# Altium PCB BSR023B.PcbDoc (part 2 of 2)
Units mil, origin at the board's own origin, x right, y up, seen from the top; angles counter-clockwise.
Board outline 3000 x 3000 mil, 4 copper layers (Top Layer, MidLayer 1, Mid Layer 2, Bottom Layer), stack 60.8 mil thick; 95 components, 24 nets, 183 pads, 215 vias.
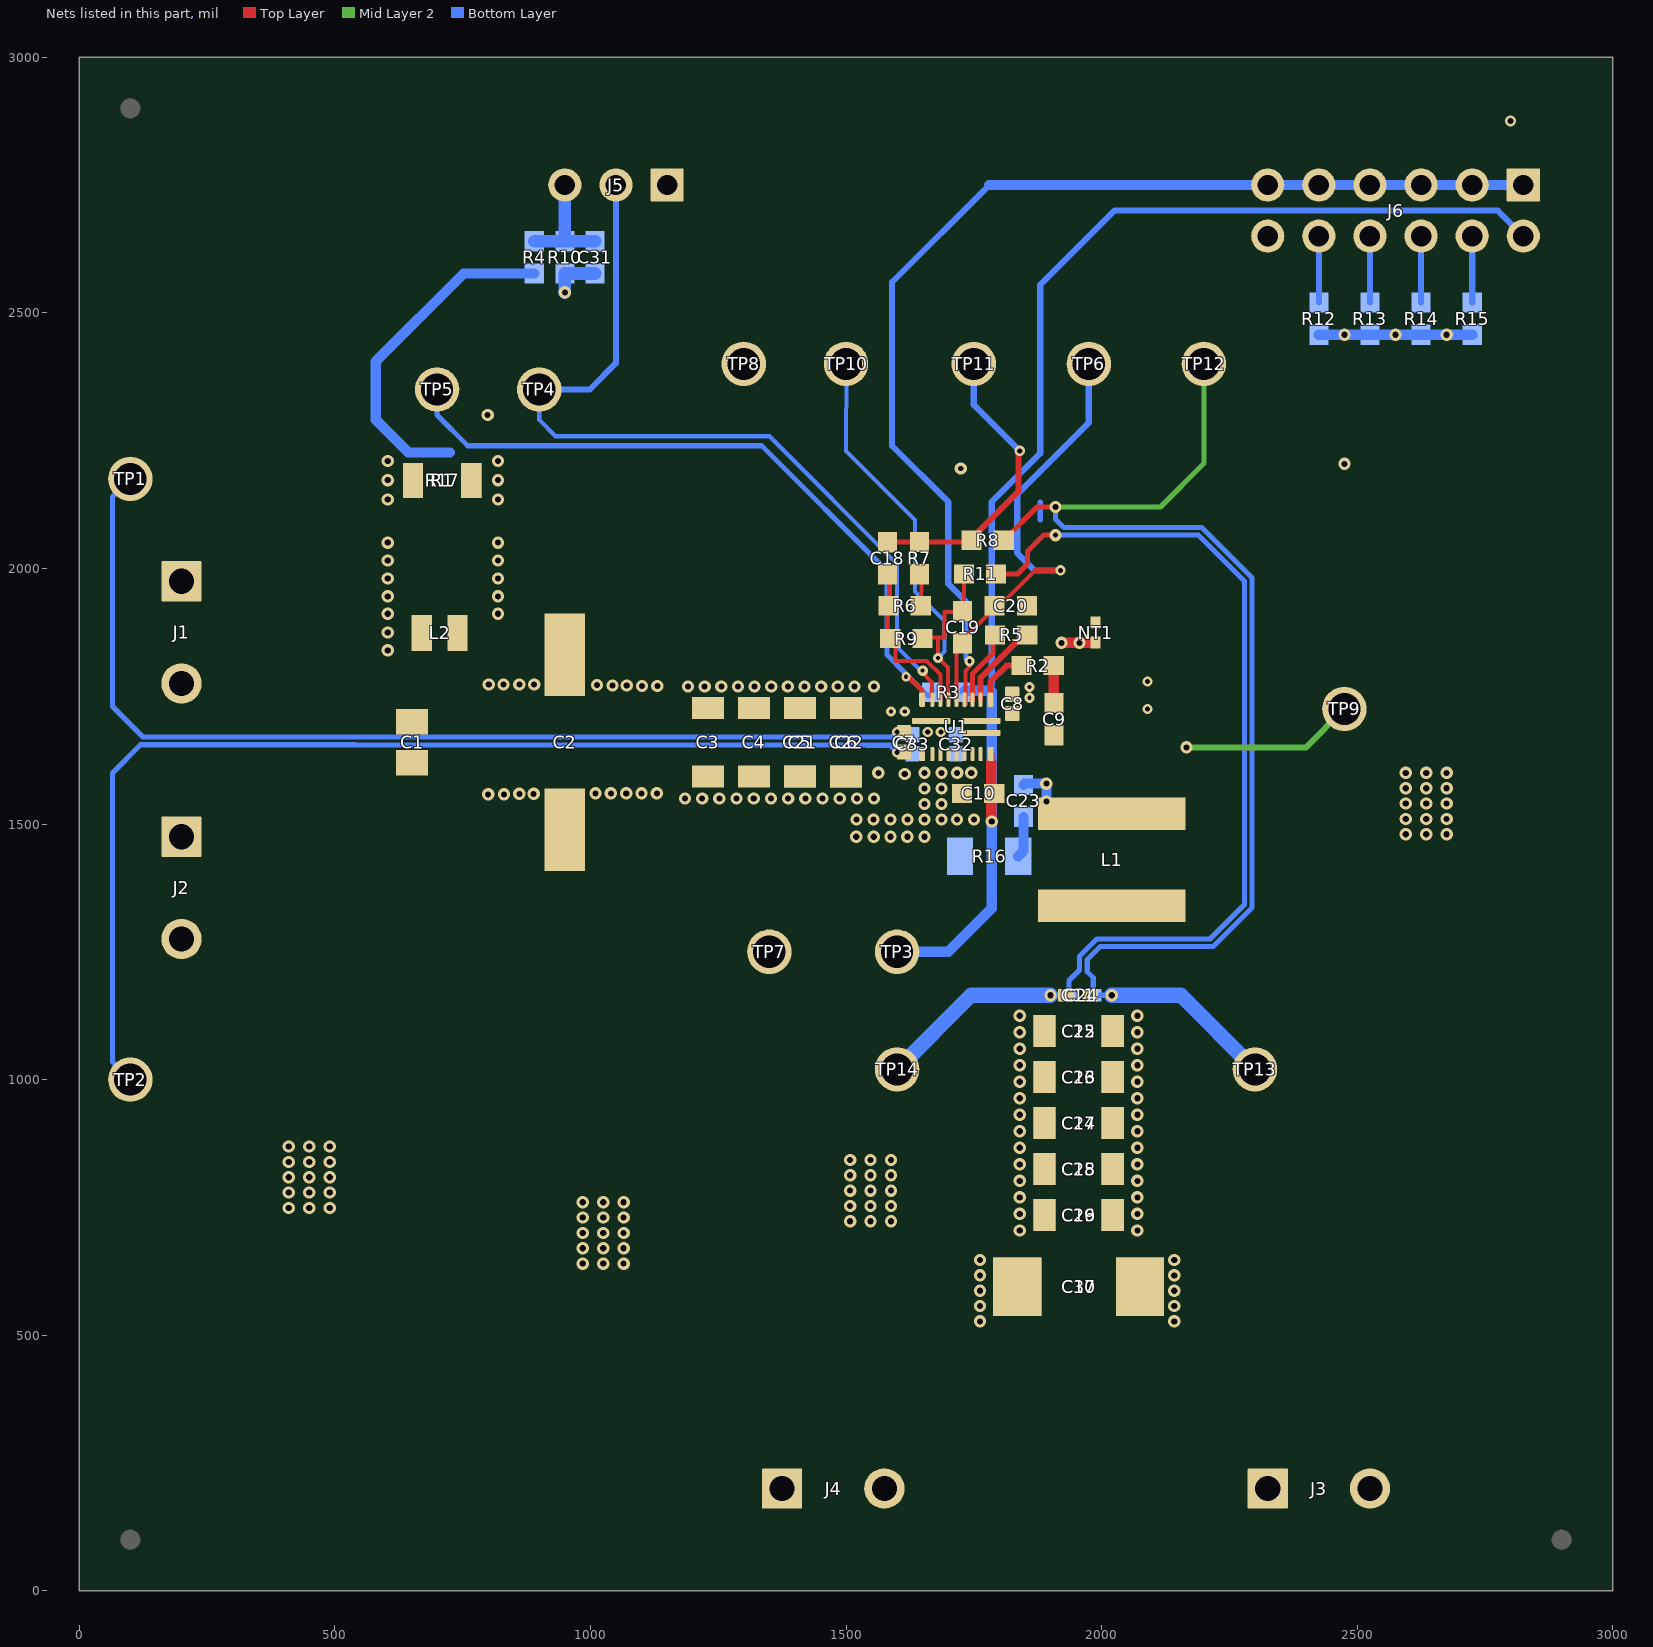
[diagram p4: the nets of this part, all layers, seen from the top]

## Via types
v1: diameter 24, hole 12, Top Layer to Bottom Layer, tented both sides, 196 vias
v2: diameter 20, hole 10, Top Layer to Bottom Layer, tented both sides, 8 vias
v3: diameter 20, hole 8, Top Layer to Bottom Layer, tented both sides, 7 vias
v4: diameter 24, hole 10, Top Layer to Bottom Layer, tented both sides, 2 vias
v5: diameter 18, hole 8, Top Layer to Bottom Layer, tented both sides, 1 vias
v6: diameter 22, hole 12, Top Layer to Bottom Layer, tented both sides, 1 vias

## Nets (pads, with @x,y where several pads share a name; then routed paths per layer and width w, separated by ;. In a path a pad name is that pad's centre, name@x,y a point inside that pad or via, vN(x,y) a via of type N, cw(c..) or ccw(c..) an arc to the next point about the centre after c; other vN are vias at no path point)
AGND: C20.2 C31.2 J5.1 J6.12 NT1.1 R5.1 R10.1 R12.1 R13.1 R14.1 R15.2 TP8.1 U1.2 | length 572.9
  Top Layer w10: 1763.24,1763.24 1763.4,1763.09 U1.2@1763.4,1743.15
  Top Layer w12: 1763.24,1763.24 1763.24,1786.51 R5.1@1845.32,1868.58
  Top Layer w20: R5.1@1845.32,1874.97 1845.32,1870 R5.1@1854.54,1870 R5.1@1857.9,1870
  Bottom Layer w20: R12.1@2425,2457.01 v1(2475,2457.01) R13.1@2525,2457.01 v1(2575,2457.01) R14.1@2625,2457.01 v1(2675,2457.01) R15.2@2725,2457.01
  Bottom Layer w25: v1(950,2540) R10.1@950,2577.01 C31.2@1008.9,2577.01
EN: J5.2 TP4.1 U1.8 | length 1694.8
  Top Layer w8: v3(1649.99,1800) 1645.47,1800 1668.54,1776.93 U1.8@1668.54,1747.55
  Bottom Layer w8: TP4.1@900,2350 900,2290 931.45,2258.55 1350,2258.55 1600,2008.55 1600,1845.87 1645.87,1800 v3(1649.99,1800)
  Bottom Layer w12: TP4.1@900,2350 998.8,2350 1050,2401.2 J5.2@1050,2750
Mode: J6.1 J6.3 J6.5 J6.7 J6.9 J6.11 U1.4 | length 2213.9
  Top Layer w7.4: U1.4@1731.75,1731.4 1734.86,1734.51 1734.86,1736.41 1733.54,1737.73 1733.54,1799.53 1741.64,1807.63 v3(1741.64,1818.35)
  Bottom Layer w10: 1735,1925 1735,1823.18 1741.64,1816.54 v3(1741.64,1818.35)
  Bottom Layer w12: 1735,1925 1735,1935 1700,1970 1700,2130 1590,2240 1590,2560 1780,2750
  Bottom Layer w20: 1780,2750 J6.11@2325,2750 J6.9@2425,2750 J6.7@2525,2750 J6.5@2625,2750 J6.3@2725,2750 J6.1@2825,2750
NetC1_1: C1.1 J1.1 J1.2 L2.1 R1.1 R17.1
  other v1: 603.5,1839.69 603.5,1874.51 603.5,1911.32 603.5,1945.39 603.5,1980.39 603.5,2015.39 603.5,2050.39 603.5,2135 603.5,2172.61 603.5,2210
NetC9_1: C9.1 C23.1 L1.1 TP9.1 U1.20 | length 421.1
  Mid Layer 2 w12: v1(2166,1650) 2400,1650 TP9.1@2475,1725
  Bottom Layer w20: C23.1@1847,1576.5 1849.5,1579 v1(1892,1579) v1(1892,1544)
NetC9_2: C9.2 R2.2 | length 73.7
  Top Layer w10: C9.2@1906.5,1737 C9.2@1907,1736.5
  Top Layer w20: C9.2@1906.5,1737 R2.2@1906.5,1810
NetC18_1: C18.1 R7.2 R8.2 TP11.1 | length 579.6
  Top Layer w10: C18.1@1576.69,2051.57 1581.03,2051.57 R8.2@1736.81,2051.57
  Top Layer w12: R8.2@1748.35,2060.93 1837.35,2149.93 1837.35,2227.48 1840,2224.83 v2(1840,2230)
  Bottom Layer w12: TP11.1@1750.5,2399.87 1750,2320 v2(1840,2230)
NetC18_2: C18.2 R6.1 R9.1 U1.7 | length 303.4
  Top Layer w7.8: R6.1@1580.64,1909.72 1580.64,1879.98 1597.24,1863.38 1597.24,1818.9 1657.82,1818.9 1684.41,1792.31 U1.7@1684.41,1747.55
  Top Layer w10: R6.1@1585.32,1919.63 C18.2@1585.32,1982.38
NetC19_1: C19.1 C20.1 TP6.1 U1.5 | length 905.7
  Top Layer w8: U1.5@1716,1743.15 1716,1848.56 1805,1937.56 1805,1931.25 1869.97,1996.22
  Top Layer w10: 1869.97,1996.22 v2(1919.57,1996.22)
  Bottom Layer w12: v2(1919.57,1996.22) 1868.63,1996.22 1835,2029.85 1835,2145 1975,2285 TP6.1@1975,2400
NetC19_2: C19.2 R9.2 R11.2 TP10.1 U1.6 | length 987.1
  Top Layer w8: R9.2@1655.81,1864.99 1692.78,1864.99 1692.53,1915 1726.76,1915 C19.2@1728.26,1916.5 ; 1680,1864.99 1680,1826.05 1699.75,1806.3 ; 1699.75,1804.89 1699.75,1743.65 U1.6@1700.25,1743.15 ; C19.2@1730.76,1914 R11.2@1730.76,1989.2
  Bottom Layer w7.8: TP10.1@1500.5,2399.87 1500,2230 1635,2095 1635,1955 1693.04,1896.96 1693.04,1837.27 v3@1680.91,1825.13
  other v3: 1680,1825
NetC23_2: C23.2 R16.2 | length 80.6
  Bottom Layer w20: R16.2@1837.09,1437 1847,1446.91 C23.2@1847,1513.5
NetC31_1: C31.1 J5.3 R4.1 R10.2 | length 228.8
  Bottom Layer w25: R4.1@890.13,2640 R10.2@950,2640 ; J5.3@950,2750 R10.2@950,2640 ; C31.1@1008.9,2640 R10.2@950,2640
NetJ6_4: J6.4 R15.1 | length 130
  Bottom Layer w12: R15.1@2725,2520 J6.4@2725,2650
NetJ6_6: J6.6 R14.2 | length 130
  Bottom Layer w12: R14.2@2625,2520 J6.6@2625,2650
NetJ6_8: J6.8 R13.2 | length 130
  Bottom Layer w12: R13.2@2525,2520 J6.8@2525,2650
NetJ6_10: J6.10 R12.2 | length 130
  Bottom Layer w12: R12.2@2425,2520 J6.10@2425,2650
NetR2_1: R2.1 U1.1 | length 111.8
  Top Layer w12: U1.1@1782.93,1743.15 1782.93,1778.92 1814.01,1810 R2.1@1846.08,1810
NetR5_2: R5.2 U1.3 | length 160.8
  Top Layer w8: R5.2@1804.85,1874.85 R5.2@1804.85,1880
  Top Layer w10: U1.3@1747.48,1743.17 1747.24,1743.4 1747.24,1793.86 1787.5,1834.12 1787.5,1857.5 R5.2@1804.85,1874.85
NetR6_2: R6.2 R7.1 | length 53
  Top Layer w8: R6.2@1646.14,1927 R7.1@1648.94,1979.91
PGND: C1.2 C2.2 C3.2 C4.2 C5.2 C6.2 C7.2 C8.2 C10.2 C11.2 C12.2 C13.2 C14.2 C15.2 C16.2 C17.2 C21.2 C22.2 C24.2 C25.2 C26.2 C27.2 C28.2 C29.2 C30.2 C32.2 C33.2 J2.1 J2.2 J4.1 J4.2 NT1.2 R11.1 R16.1 TP2.1 TP7.1 TP14.1 U1.11 U1.12 U1.13 U1.14 U1.15 U1.16 U1.17 U1.18 | length 4325.6
  Top Layer w10: R11.1@1793.75,1989.2 1835.45,1989.2 1854.85,2008.6 ; 1854.85,2010 1854.85,2033.39 1886.46,2065 v4(1910,2065) ; v1@1950,1850 v1@1950.31,1850.31
  Top Layer w20: v1(1921.69,1854.38) v1(1956.69,1854.38) ; v1@1957,1854.7 NT1.2@1988.34,1854.7
  Bottom Layer w10: TP2.1@100,1000 65,1035 65,1600 120,1655 540,1655 1540.87,1654.13 1585.87,1654.13 v2(1600,1640) ; 1880,2095 1880,2130 ; v1(1900,1165) C24.2@1936.38,1165 1936.38,1193.88 1957,1214.5 1957,1241.34 1990.66,1275 2211.84,1275 2279.5,1342.66 2279.5,1975.09 2189.59,2065 v4(1910,2065)
  Bottom Layer w30: TP14.1@1600,1020 1745,1165 v1(1900,1165)
  other v1: 1762.26,527 1762.26,557 1762.26,587 1762.26,617 985,640 1025,640 1065,640 1762.26,647 985,670 1025,670 1065,670 985,700 1025,700 1065,700 1840,705 1508.06,722.8 1548.06,722.8 1588.06,722.8 985,730 1025,730 1065,730 1840,737.31 410,749 450,749 490,749 1508.06,752.8 1548.06,752.8 1588.06,752.8 985,760 1025,760 1065,760 1840,769.62 410,779 450,779 490,779 1508.06,782.8 1548.06,782.8 1588.06,782.8 1840,801.92 410,809 450,809 490,809 1508.06,812.8 1548.06,812.8 1588.06,812.8 1840,834.23 410,839 450,839 490,839 1508.06,842.8 1548.06,842.8 1588.06,842.8 1840,866.54 410,869 450,869 490,869 1840,898.85 1840,931.15 1840,963.46 1840,995.77 1840,1028.08 1840,1060.38 1840,1092.69 1840,1125 1520,1475 1554.34,1475 1587.09,1475 1620,1475 1653.54,1475 2595,1480 2635,1480 2675,1480 1520.63,1508.63 1553.86,1508.63 1587.09,1508.63 1620.32,1508.63 1653.54,1508.63 1686.77,1508.63 1717.26,1508.63 1750.49,1508.63 2595,1510 2635,1510 2675,1510 1653.54,1539.08 1686.77,1539.08 2595,1540 2635,1540 2675,1540 1185,1550 1218.64,1550 1252.27,1550 1285.91,1550 1319.55,1550 1353.18,1550 1386.82,1550 1420.45,1550 1454.09,1550 1487.73,1550 1521.36,1550 1555,1550 800,1558 831,1558 861,1559 889,1559 1010,1560 1040,1560 1070,1560 1100,1560 1130,1560 1653.54,1569.54 1686.77,1569.54 2595,1570 2635,1570 2675,1570 1615,1597.84 1563.27,1600 1653.54,1600 1686.77,1600 1717.45,1600 1745,1600 2595,1600 2635,1600 2675,1600 2475,2204.54 799,2300
  other v2: 2090,1725 2090,1779
  other v3: 1859,1747 1859,1768
  other v4: 1724.39,2195.63
  other v6: 2800,2875
PGOOD: R3.2 TP5.1 U1.9 | length 1410.5
  Top Layer w10: v5@1619.48,1789.99 1648.98,1760.49 U1.9@1648.98,1747.55
  Bottom Layer w10: TP5.1@700,2350 700,2300 760,2240 1335,2240 1580,1995 1580,1831 1617.6,1793.4 v5(1617.6,1788.1) 1622.9,1788.1 1660.89,1750.11 1668.5,1757.73 R3.2@1668.5,1765
VCC: C10.1 J6.2 R3.1 TP3.1 U1.19 | length 2689.8
  Top Layer w15: 1782.93,1620.09 U1.19@1782.93,1636.85
  Top Layer w20: 1784.15,1620.09 1784.15,1505.62 v1(1785.02,1504.76)
  Bottom Layer w12: 1785.02,1759.29 1783.58,1760.73 1785,1775 1785,2130 1880,2225 1880,2555 2025,2700 2775,2700 J6.2@2825,2650
  Bottom Layer w20: TP3.1@1600,1250 1700,1250 1785.02,1335.02 v1(1785.02,1504.76) 1785.02,1759.29 ; R3.1@1732.24,1760.73 1783.58,1760.73
VIN: C2.1 C3.1 C4.1 C5.1 C6.1 C7.1 C8.1 C21.1 C22.1 C32.1 C33.1 L2.2 R1.2 R4.2 R17.2 TP1.1 U1.10 U1.21 | length 2690.6
  Bottom Layer w10: TP1.1@100,2175 65,2140 65,1730 125,1670 1590,1670 v2(1600,1680)
  Bottom Layer w20: 725.05,2227 643.63,2227 580,2290.63 580,2405 752.01,2577.01 R4.2@890.13,2577.01
  other v1: 1191,1769 1223.55,1769 1256.09,1769 1288.64,1769 1321.18,1769 1353.73,1769 1386.27,1769 1418.82,1769 1451.36,1769 1483.91,1769 1516.45,1769 1555,1769 1101,1770 1131,1770 1043,1771 1071,1771 1013,1772 801,1773 830,1773 861,1773 890,1773 819.08,1911.32 819.08,1945.39 819.08,1980.39 819.08,2015.39 819.08,2050.39 819.08,2135 819.08,2172.61 819.08,2210
  other v2: 1660,1680 1685.51,1680
  other v3: 1588.06,1720 1615,1720
Vout: C11.1 C12.1 C13.1 C14.1 C15.1 C16.1 C17.1 C24.1 C25.1 C26.1 C27.1 C28.1 C29.1 C30.1 J3.1 J3.2 L1.2 R8.1 TP12.1 TP13.1 | length 2564.9
  Top Layer w10: R8.1@1808.71,2055 1873.71,2120 v1(1910,2120)
  Mid Layer 2 w10: v1(1910,2120) 2115,2120 2200,2205 TP12.1@2200.5,2399.87
  Bottom Layer w10: v1(1910,2120) 1910,2096.11 1926.11,2080 2195.8,2080 2294.5,1981.3 2294.5,1336.44 2218.06,1260 1996.88,1260 1972,1235.12 1972,1210.98 1983.62,1199.35 C24.1@1983.62,1165 v1(2020,1165)
  Bottom Layer w30: v1(2020,1165) 2155,1165 TP13.1@2300,1020
  other v1: 2142.26,527 2142.26,557 2142.26,587 2142.26,617 2142.26,647 2070,705 2070,737.31 2070,769.62 2070,801.92 2070,834.23 2070,866.54 2070,898.85 2070,931.15 2070,963.46 2070,995.77 2070,1028.08 2070,1060.38 2070,1092.69 2070,1125
pads on no net: FID1.1 FID2.1 FID3.1 FID4.1 FID5.1 FID6.1 H1.0 H2.0 H3.0 H4.0 LBL1.0 SH-J1.0 SH-J2.0 U1.10A U1.10B U1.20A U1.20B U1.21A U1.21B

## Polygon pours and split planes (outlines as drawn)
AGND on Top Layer "TOP_LAYER_AGND_P102" (solid, remove dead copper, pour order 102): 1885.42,1840.83 1880.86,1836.26 1836.77,1836.26 1836.77,1810.3 1589.42,1810.3 1589.42,2158.11 1491.15,2233.8 3.42,2233.8 3.42,2949.3 2976.84,2949.3 2974.58,1871.35 1885.42,1871.35
VIN on Top Layer "TOP_LAYER_VIN_P084" (solid, remove dead copper, pour order 84): 710,1664 1720,1664 1720,1690.34 1848,1690.34 1854.16,1696.5 1854.16,1738.31 1810.16,1738.31 1810,1730 1630,1730 1629,1731 1629,1763 1623,1763 1584,1802 1587,1805 1587,2227 710,2227
no net on Top Layer "Top Layer-No Net 1" (solid, pour order 150): 1885.53,1996.22 1885.53,1996.2 1874.33,1985 1875,1984.33 1875,1983.13
no net on Top Layer "TOP_LAYER_NONET_P142" (solid, remove dead copper, pour order 142): -40,2155
NetC1_1 on Top Layer "TOP_LAYER_NETC1_1_P140" (solid, remove dead copper, pour order 140): 0,2236.37 695,2236.37 695,1655 0,1655
PGND on Top Layer "TOP_LAYER_PGND_P126" (solid, remove dead copper, pour order 126): 2011.2,1840 1975,1805.48 1975,1700 2190,1700 2190,1416 2975,1416 2975,1840
NetC9_1 on Top Layer "Top Layer-No Net" (solid, remove dead copper, pour order 76): 1791.29,1659.71 1803,1648 1803,1619.57 1817,1607.57 1817,1470 2183.44,1470 2183.44,1694 1722.17,1695 1722.17,1672.27 1722.17,1659.71
PGND on Top Layer "TOP_LAYER_PGND_P080" (solid, remove dead copper, pour order 80): 9.45,1653 11.45,1655 1717.45,1655 1717.45,1653 1771.45,1653 1771.45,1564 1772.45,1563 1771.45,1563 1771.45,1501.55 1797.45,1501.55 1797.45,1458.22 1797.45,1461 1816,1461 1837,1461 1837,1191 1841.89,1185 1950.45,1185 1950.45,25 5.61,25
Vout on Top Layer "TOP_LAYER_VOUT_P130" (solid, remove dead copper, pour order 130): 2965,1409 1837,1409 1837,1136 1957,1136 1952.29,25 2965,25
PGND on Bottom Layer "BOTTOM_LAYER_PGND_P148" (solid, remove dead copper, pour order 148): 0,3000 0,0 3000,0 3000,3000
NetC1_1 on Bottom Layer "BOTTOM_LAYER_NETC1_1_P124" (solid, remove dead copper, pour order 124): 0,2225 695,2225 695,1665 678.16,1665 0,1665
VIN on Bottom Layer "BOTTOM_LAYER_VIN_P092" (solid, remove dead copper, pour order 92): 713.44,2300 713.44,1660 1736.13,1660 1735.71,1796.43 1710,1800 1589.98,1800 1588,2226 1514,2300
Vout on Bottom Layer "BOTTOM_LAYER_VOUT_P132" (solid, remove dead copper, pour order 132): 1962.79,1185 2975,1185 2975,25 1959.83,25
PGND on Mid Layer 2 "MID_LAYER_2_PGND_P128" (solid, remove dead copper, pour order 128): 2975,3000 40.34,3000 40.34,25 1950,25 1950,1180 1955,1185 2975,1185
Vout on Mid Layer 2 "MID_LAYER_2_VOUT_P120" (solid, remove dead copper, pour order 120): 1960.4,30 1960.4,1180 2975,1180 2975,30
PGND on MidLayer 1 "MIDLAYER_1_PGND_P108" (solid, remove dead copper, pour order 108): -13.84,-26.27 2990.16,-26.27 2990.16,1769.73 2990.16,2973.73 -13.84,2973.73

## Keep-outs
Top Layer:
  circle w5: c100,1000 r56.57
  circle w5: c100,2175 r56.57
MidLayer 1:
  circle w0: c1600,1640 r20
  circle w5: c100,1000 r56.57
Mid Layer 2:
  circle w0: c1600,1640 r20
  circle w5: c100,1000 r56.57
Keep-Out Layer:
  the board outline again, w8
  text ".Layer_Name" at 577,-1308.49 h60

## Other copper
Top Layer:
  pour cut-out: 1540,1080 1540,960 1660,960 1660,1080
  pour cut-out: 2359.87,1079.75 2360,960 2240,960 2240,1080.25
  pour cut-out: 1836.35,1806 1836.35,2046 1660.35,2046 1660.35,1806
  region net PGND: 1810,1778.28 1870.16,1778.28 1870.16,1737.31 1855.16,1737.31 1810,1737.31
  text ".Layer_Name" at 577,-1308.49 h60
MidLayer 1:
  pour cut-out: 1925,1171.07
  pour cut-out: 1898.55,1187.75
  pour cut-out: 1868.11,1190 1868.11,1143.84 1928.34,1143.84 1929,1144.5 1928.34,1190.77
  pour cut-out: 1930.39,2085.39 1930.39,2044.61 1890.25,2044.61 1890.25,2085.39
  pour cut-out: 1916.68,2075
  pour cut-out: 1916.68,2075
  pour cut-out: 1917.8,2083.84
  pour cut-out: 1883.7,2079.47
  pour cut-out: 1924.42,2079.42
  pour cut-out: 1899.02,2065
  pour cut-out: 1540,1080 1540,960 1660,960 1660,1080
Mid Layer 2:
  pour cut-out: 2047.63,1132.38 2047.93,1133.19 2047.93,1172.8 2047.93,1188.52 1975.88,1188.52 1975.88,1132.31 1976.61,1131.58
  pour cut-out: 1932.51,1136.4 1932.8,1137.21 1932.8,1176.82 1932.8,1192.54 1875,1192.54 1875,1135.75
  pour cut-out: 1930.39,2085.39 1930.39,2044.61 1890.25,2044.61 1890.25,2085.39
  pour cut-out: 1924.42,2080 1924.42,2050 1890.25,2050 1890.25,2080
  pour cut-out: 1904.02,2055
  pour cut-out: 1540,1080 1540,960 1660,960 1660,1080
  pour cut-out: 2359.87,1079.75 2360,960 2240,960 2240,1080.25
Bottom Layer:
  pour cut-out: 1885,1185 1735,1185 1630,1080 1540,1080 1540,960 1660,960 1660,1046.69 1758.7,1145.39 1885,1145.39
  pour cut-out: 2035,1185.5 2163.86,1185.5 2269.87,1079.5 2359.87,1079.5 2359.87,959.5 2239.87,959.5 2239.87,1048.02 2141.73,1146.16 2035,1146.16
  pour cut-out: 1983.62,1229.09 2005,1250.46 2228,1250.46 2313.44,1335.91 2313.44,1984.02 2203,2094.46 1959,2094.46 1939,2114.46 1939,2144.46 1889,2144.46 1889,2047.76 2181.7,2047.76 2260,1969.46 2260,1345.32 2201.87,1287.19 1985.25,1287.19 1942.19,1244.13 1942.19,1217.59 1928.29,1203.69 1885,1203.69 1885,1138.45 2034.42,1138.46 2034.42,1203.69 1999.77,1203.69 1983.62,1219.84
  pour cut-out: 75,1690 1583.15,1690 1583.15,1695 1615.94,1695 1615.94,1625 1583.15,1625 1583.15,1640 75,1640
  pour cut-out: 42.52,2236.37 46.15,2240 160,2240 160,2140.28 90,2070.28 90,1740 140,1690 140,1630 90,1580 90,1110 160,1040 160,940 40,940
  text ".Layer_Name" at 577,-1308.49 h60

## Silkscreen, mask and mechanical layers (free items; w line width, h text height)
Top Overlay:
  lines w20: 1785.87,1785.99 1790,1785.99
  text "EN" at 990.83,2835 h70
  text "ON" at 740,2719.47 h70
  text "OFF" at 1255,2719.47 h70
  text "VSNS+" at 1642.06,2490 h40
  text "Skip 600kHZ" at 2845,2200 h72.83 r90
  text "Skip 800kHZ" at 2747.71,2181.53 h72.83 r90
  text "Skip 1000kHZ" at 2650,2142 h72.83 r90
  text "FCCM 600kHZ" at 2350,2140 h72.83 r90
  text "FCCM 800kHZ" at 2440,2140 h72.83 r90
  text "FCCM 1000kHZ" at 2550,2105 h72.83 r90
  text "VIN" at 430,1905 h50
  text "PGND" at 433.84,1215 h50
  text "HOT SURFACE" at 2077.8,1110.75 h120
  text "Iin max = 12A" at 237.82,1096.48 h72.83
  text "PGND" at 1400,425 h40
  text "VOUT" at 2350,425 h40
  text "Iout max = 20A" at 1724,53 h72.83
  text ".Layer_Name" at 577,-1308.49 h60
Bottom Overlay:
  text "VIN" at 350,1937.6 h50 r90
  text "PGND" at 350,1470 h50 r90
  text "PGND" at 1550,305 h40
  text "VOUT" at 2475,305 h40
  text ".Layer_Name" at 577,-1308.49 h60
Top Paste:
  text ".Layer_Name" at 577,-1308.49 h60
Bottom Paste:
  text ".Layer_Name" at 577,-1308.49 h60
Top Solder:
  rectangle: 713.44,1845 784.44,2054.02
  rectangle: 625,1836.51 695,2054.02
  region: 1865,1400 1865,1349 1865,1225 2180,1225 2180,1400
  region: 1865,1627 1865,1468 2179,1468 2179,1627
  text ".Layer_Name" at 577,-1308.49 h60
  text ".Layer_Name" at 577,-1308.49 h60
Bottom Solder:
  rectangle: 1290,1191.87 1410,1311.87
  rectangle: 140,1215 260,1335
  rectangle: 140,1415 260,1535
  rectangle: 140,1715 260,1835
  rectangle: 140,1915 260,2035
  rectangle: 1315,140 1435,260
  rectangle: 1515,140 1635,260
  rectangle: 2265,140 2385,260
  rectangle: 2465,140 2585,260
  text ".Layer_Name" at 577,-1308.49 h60
Drill Guide:
  text ".Layer_Name" at 577,-1308.49 h60
M1 Board Outline:
  the board outline again, w10
  text ".Layer_Name" at 577,-1308.49 h60
M2 Board Dimensions:
  rectangle: 0,-725 125,-600
  rectangle: 125,-850 500,-725
  lines w7: 0,-725 1000,-725 ; 125,-850 125,-600 ; 250,-850 250,-600 ; 500,-850 500,-600 ; 750,-850 750,-600 ; 0,-850 1000,-850 1000,-600 0,-600 0,-850
  text ".Layer_Name" at 577,-1308.49 h60
M3 3D STEP Top:
  text ".Layer_Name" at 577,-1308.49 h60
M4 3D STEP Bottom:
  text ".Layer_Name" at 577,-1308.49 h60
M5 Assembly Top:
  lines w10: -292,-1380.17 6308,-1380.17 ; -292,-1176.83 6310,-1176.83 ; -292,-973.5 -292,-1583.5 3713,-1583.5 6310,-1583.5 6310,-973.5 -291.5,-973.5 -291.5,-1583.5 1284,-1583.5 ; 2173,-1583.5 2173,-973.5 ; 3440,-1176.83 3440,-973.5 ; 4280,-1176.83 4280,-973.5 ; 4902,-1590 4902,-1387.17
  text "COMPONENTS MARKED 'DNP' SHOULD NOT BE POPULATED." at 1153.5,-768.5 h60
  text "ASSEMBLY VARIANT:" at 1153,-884 h60
  text ".VariantName" at 2189,-884 h60
  text "PCB VIEWED FROM TOP SIDE" at -228.5,-1105.67 h60
  text "BOARD #:" at 2248,-1105.67 h60
  text ".PRJ_Number" at 2793.5,-1105.67 h60
  text "REV:" at 3638,-1105.67 h60
  text ".PCB_Rev" at 3929.5,-1105.67 h60
  text "SVN REV:" at 4476,-1105.67 h60
  text ".VersionControl_RevNumber" at 4982,-1105.67 h60
  text "TID #:" at 2248,-1309 h60
  text ".TID" at 2793.5,-1309 h60
  text "PLOT NAME =" at -228.5,-1514.34 h60
  text ".plot_File_Name" at 577,-1514.34 h60
  text "GENERATED    :" at 2250,-1514.34 h60
  text ".Print_Date" at 3119.5,-1514.34 h60
  text ".Print_Time" at 3848.5,-1514.34 h60
  text "TEXAS INSTRUMENTS" at 5113,-1514.34 h60
M6 Assembly Bottom:
  lines w10: -292.5,-1177.33 6309.5,-1177.33 ; -290.5,-1380.67 6309.5,-1380.67 ; 1115.5,-1590.5 1115.5,-1387.67 ; 1737.5,-1177.33 1737.5,-974 ; 2577.5,-1177.33 2577.5,-974 ; 3844.5,-1584 3844.5,-974 ; 4733.5,-1584 6309,-1584 6309,-974 -292.5,-974 -292.5,-1584 2304.5,-1584 6309.5,-1584 6309.5,-974
  text "COMPONENTS MARKED 'DNP' SHOULD NOT BE POPULATED." at 6102,-768 h60
  text ".VariantName" at 5058,-884 h60
  text "ASSEMBLY VARIANT:" at 6097,-884 h60
  text ".VersionControl_RevNumber" at 1035.5,-1106.17 h60
  text "SVN REV:" at 1541.5,-1106.17 h60
  text ".PCB_Rev" at 2088,-1106.17 h60
  text "REV:" at 2379.5,-1106.17 h60
  text ".PRJ_Number" at 3224,-1106.17 h60
  text "BOARD #:" at 3769.5,-1106.17 h60
  text "PCB VIEWED FROM BOTTOM SIDE" at 6246,-1106.17 h60
  text ".TID" at 3224,-1309.5 h60
  text "TID #:" at 3769.5,-1309.5 h60
  text "TEXAS INSTRUMENTS" at 904.5,-1514.84 h60
  text ".Print_Time" at 2169,-1514.84 h60
  text ".Print_Date" at 2898,-1514.84 h60
  text "GENERATED    :" at 3767.5,-1514.84 h60
  text ".plot_File_Name" at 5440.5,-1514.84 h60
  text "PLOT NAME =" at 6246,-1514.84 h60
M9 Title Sheet:
  drawing of 57 lines, arcs and shapes, not listed
  text "1" at 739.84,7586.5 h70
  text "2" at 3235.5,7586.5 h70
  text "3" at 5724.84,7586.5 h70
  text "4" at 8231.51,7586.5 h70
  text "5" at 10730.5,7586.5 h70
  text "6" at 13235.5,7586.5 h70
  text "A" at -416.5,6443.5 h70
  text "A" at 14383.5,6443.5 h70
  text "B" at -416.5,4063.5 h70
  text "B" at 14383.5,4063.5 h70
  text "C" at -416.5,1688.5 h70
  text "C" at 14383.5,1688.5 h70
  text "PROJECT TITLE:" at 11343.5,-172.5 h45
  text ".PRJ_Title" at 11393.5,-305.83 h70
  text "DESIGNED FOR:" at 11343.5,-473.5 h45
  text ".PRJ_Customer" at 11393.5,-613.5 h70
  text "D" at -416.5,-681.5 h70
  text "D" at 14383.5,-681.5 h70
  text "FILE NAME:" at 11343.5,-773.5 h45
  text ".PCB_File_Name_No_Path" at 11393.5,-893.5 h70
  text "Texas Instruments (TI) and/or its licensors do not warrant the accuracy or completeness of this specification" at 6374,-1055.34 h45
  text "ENGINEER:" at 11343.5,-1063.5 h45
  text "LAYOUT BY:" at 12848.5,-1063.5 h45
  text "or any information contained therein. TI and/or its licensors do not warrant that this design will meet" at 6329.01,-1168 h45
  text ".PRJ_Engineer" at 11393.5,-1218.49 h70
  text ".PCB_Layout" at 12899,-1218.49 h70
  text "the specifications, will be suitable for your application or fit for any particular purpose, or will operate in" at 6329.01,-1280.67 h45
  text ".Layer_Name" at 577,-1308.49 h60
  text "ALTIUM DESIGNER VERSION:" at 12848.5,-1373.5 h45
  text "an implementation. TI and/or its licensors do not warrant that the design is production worthy. You should" at 6329.01,-1393.33 h45
  text "completely validate and test your design implementation to confirm the system functionality for your application." at 6374,-1506 h45
  text ".print_Scale" at 11393.5,-1506.83 h70
  text ".Application_BuildNumber" at 12899,-1506.83 h70
  text "1" at 739.84,-1713.5 h70
  text "2" at 3235.5,-1713.5 h70
  text "3" at 5724.84,-1713.5 h70
  text "4" at 8231.51,-1713.5 h70
  text "5" at 10730.5,-1713.5 h70
  text "6" at 13235.5,-1713.5 h70
M10 Fab Notes:
  drawing of 173 lines, arcs and shapes, not listed
  text "DESIGN INFORMATION" at 12378.02,5751 h60
  text "MIN. TRACK WIDTH:" at 11733.46,5571 h60
  text "8" at 12829.7,5571 h60
  text "MIL" at 12984.46,5571 h60
  text "MIN. CLEARANCE:" at 11733.46,5439 h60
  text "0.2" at 12769.7,5439 h60
  text "mm" at 12984.46,5439 h60
  text "MIN. VIA PAD SIZE:" at 11733.46,5307 h60
  text "24" at 12799.71,5307 h60
  text "MIL" at 12984.46,5307 h60
  text "0.05mm (2MIL)" at 12428.46,5165.29 h60
  text "MINIMUM ANNULAR RING" at 11404.23,5161 h60
  text "EXTERNAL" at 13136.46,5161 h60
  text "PER" at 11604.23,5043 h60
  text "IPC-D-275 CLASS 2 LEVEL C" at 11824.23,5043 h60
  text "MIL, HOLES" at 13312.46,4930.71 h60
  text "+/-" at 12920,4930 h60
  text "+/-" at 13774,4930 h60
  text "REGISTRATION TOLERANCES:" at 11404.23,4925 h60
  text "METAL" at 12604,4925 h60
  text "5" at 13180.2,4925 h60
  text "3" at 14013.2,4925 h60
  text "MIL" at 14129.46,4925 h60
  text "+/-" at 13774,4812 h60
  text "HOLE SIZE TOLERANCE (UNLESS OTHERWISE SPECIFIED):" at 11404.23,4807 h60
  text "3" at 14013.2,4807 h60
  text "MIL" at 14129.46,4807 h60
  text "MATERIAL:" at 11329.46,4597.54 h60
  text "FR-4 High Tg" at 12315.9,4457.21 h60
  text "FR-408" at 11750.46,4448.64 h60
  text "OTHER" at 13238.46,4448.64 h60
  text "X" at 12161,4445 h60
  text "60 MIL +/- 10%" at 13682,4293 h72.83
  text "X" at 11940,4285.92 h60
  text "62 MIL (1.6mm) +/-10%" at 12070.56,4285.92 h60
  text "THICKNESS:" at 11404.23,4281.64 h60
  text "OTHER" at 13355.46,4281.64 h60
  text "TOLERANCE:" at 11404.23,4123.64 h60
  text "X" at 12243.53,4123.64 h60
  text "ANSI IPC-6012 TYPE 3 CLASS 2" at 12430.48,4123.64 h60
  text "OTHER +/-" at 12430.46,3967.64 h60
  text "BOW & TWIST:" at 11404.23,3810.64 h60
  text "X" at 12243.53,3810.64 h60
  text "ANSI IPC-6012 TYPE 3 CLASS 2" at 12430.48,3810.64 h60
  text "OTHER +/-" at 12430.46,3652.13 h60
  text "DRILLING:" at 11329.46,3513.64 h60
  text "REFERENCE:" at 11404.23,3396.64 h60
  text "X" at 12052.46,3396.64 h60
  text "AS SHOWN" at 12239.46,3396.64 h60
  text "X" at 12953.46,3396.64 h60
  text "NC_DRILL FILES" at 13090.46,3396.64 h60
  text "PTH COPPER THICKNESS:" at 11404.23,3238.64 h60
  text "X" at 12534.46,3238.64 h60
  text "20-30 um" at 12671.46,3238.64 h60
  text "OTHER" at 13388.46,3238.64 h60
  text "BOARD FINISH:" at 11329.46,3079.64 h60
  text "SILKSCREEN:" at 11484.68,2961.64 h60
  text "X" at 12433.46,2961.64 h60
  text "TOP" at 12559.46,2961.64 h60
  text "X" at 12943.46,2961.64 h60
  text "BOTTOM" at 13070.46,2961.64 h60
  text "SILKSCREEN COLOR:" at 11484.68,2794.64 h60
  text "X" at 12432.42,2794.64 h60
  text "WHITE" at 12559.46,2794.64 h60
  text "OTHER" at 13070.46,2794.64 h60
  text "X" at 12563.42,2635.44 h60
  text "GREEN" at 12690.46,2635.44 h60
  text "OTHER" at 13308.46,2635.44 h60
  text "SOLDER RESIST COLOR:" at 11484.68,2624.64 h60
  text "X" at 12563.42,2465.44 h60
  text "MATTE" at 12690.46,2465.44 h60
  text "SEMI-GLOSS" at 13308,2464.8 h60
  text "IMMERSION GOLD (ENIG)" at 12390.46,2276.92 h60
  text "ENEPIG" at 13728,2273.64 h60
  text "SURFACE FINISH:" at 11329.46,2272.64 h60
  text "X" at 12203.51,2272.64 h60
  text "IMM. TIN/SILVER OR EQUIV" at 11659,2115.64 h60
  text "OTHER" at 13090.46,2115.64 h60
  text "X" at 12198.51,1937.64 h60
  text "ARRAY/PANEL:" at 11329.46,1936.64 h60
  text "CUT AND TRIM PER M1 BOARD OUTLINE" at 12390.46,1932.35 h60
  text "N.C. ROUTE" at 12390.46,1780.64 h60
  text "X" at 13069.46,1780.64 h60
  text "V. SCORE" at 13256.46,1780.64 h60
  text "CERTIFICATION:" at 11329.46,1643.64 h60
  text "MATERIALS AND WORKMANSHIP FOR ALL PCBS" at 12054.46,1643.64 h60
  text "TO MEET OR EXCEED THE REQUIREMENTS OF:" at 12054.46,1545.64 h60
  text "X" at 11680.96,1409.13 h60
  text "ANSI IPC-A-600F CLASS ->" at 11819.96,1409.13 h60
  text "X" at 13459.02,1409.13 h60
  text "2" at 13577.96,1409.14 h60
  text "1" at 13262.96,1407.64 h60
  text "3" at 13931.96,1407.64 h60
  text "X" at 12495.02,1249.64 h60
  text "RoHS" at 12631.96,1249.64 h60
  text "OTHER" at 13276.36,1249.64 h60
  text "PER ORDER" at 13673.42,1249.64 h60
  text "ALL BOARDS MUST MEET OR EXCEED UL94-V0 REQUIREMENTS." at 11357,1084 h60
  text "PCB MUST BEAR THE UL94V-0 UL REGISTERED MATERIAL ID NUMBER" at 11357,964 h60
  text "ADDITIONAL REQUIREMENTS:" at 11329.46,790.64 h60
  text "MICROSECTION:" at 11404.23,675.64 h60
  text "YES" at 12309.96,675.64 h60
  text "REQUIRED" at 13171.46,519.49 h60
  text "BARE BOARD ELEC. TEST:" at 11404.23,516.64 h60
  text "NONE" at 12709.96,516.64 h60
  text "X" at 13044.46,516.64 h60
  text "PER ORDER" at 13763.46,516.64 h60
  text ".Layer_Name" at 577,-1308.49 h60
M11 Gerber Information:
  lines w10: -292,-1380.17 6308,-1380.17 ; -292,-1176.83 6310,-1176.83 ; -292,-973.5 -292,-1583.5 3713,-1583.5 6310,-1583.5 6310,-973.5 -291.5,-973.5 -291.5,-1583.5 1284,-1583.5 ; 2173,-1583.5 2173,-973.5 ; 3440,-1176.83 3440,-973.5 ; 4280,-1176.83 4280,-973.5 ; 4902,-1590 4902,-1387.17
  text "ALL ARTWORK VIEWED FROM TOP SIDE" at -228.5,-1105.67 h60
  text "BOARD #:" at 2248,-1105.67 h60
  text ".PRJ_Number" at 2793.5,-1105.67 h60
  text "REV:" at 3638,-1105.67 h60
  text ".PCB_Rev" at 3929.5,-1105.67 h60
  text "SVN REV:" at 4476,-1105.67 h60
  text ".VersionControl_RevNumber" at 4982,-1105.67 h60
  text "LAYER NAME =" at -228.5,-1308.49 h60
  text "TID #:" at 2248,-1309 h60
  text ".TID" at 2793.5,-1309 h60
  text "PLOT NAME =" at -228.5,-1514.34 h60
  text ".plot_File_Name" at 577,-1514.34 h60
  text "GENERATED    :" at 2250,-1514.34 h60
  text ".Print_Date" at 3119.5,-1514.34 h60
  text ".Print_Time" at 3848.5,-1514.34 h60
  text "TEXAS INSTRUMENTS" at 5113,-1514.34 h60
M12 Stackup:
  drawing of 295 lines, arcs and shapes, not listed
  text "Layer" at 8765.34,7267.5 h60
  text "Name" at 9175.26,7267.5 h60
  text "Material" at 10105,7267.5 h60
  text "Thickness" at 10964.77,7267.5 h60
  text "Constant" at 11614.6,7267.5 h60
  text "Board Layer Stack" at 12184.46,7267.5 h60
  text "1" at 8765.34,7147.5 h60
  text "Top Overlay" at 9175.26,7147.5 h60
  text "2" at 8765.34,7027.5 h60
  text "Top Solder" at 9175.26,7027.5 h60
  text "Solder Resist" at 10105,7027.5 h60
  text "0.40mil" at 10964.77,7027.5 h60
  text "3.5" at 11614.6,7027.5 h60
  text "3" at 8765.34,6907.5 h60
  text "Top Layer" at 9175.26,6907.5 h60
  text "Copper" at 10105,6907.5 h60
  text "2.80mil" at 10964.77,6907.5 h60
  text "4" at 8765.34,6787.5 h60
  text "Dielectric1" at 9175.26,6787.5 h60
  text "FR-4 High TG" at 10105,6787.5 h60
  text "9.30mil" at 10964.77,6787.5 h60
  text "4.2" at 11614.6,6787.5 h60
  text "5" at 8765.34,6667.5 h60
  text "MidLayer 1" at 9175.26,6667.5 h60
  text "Copper" at 10105,6667.5 h60
  text "2.80mil" at 10964.77,6667.5 h60
  text "6" at 8765.34,6547.5 h60
  text "Dielectric 2" at 9175.26,6547.5 h60
  text "FR-4 High TG" at 10105,6547.5 h60
  text "31.00mil" at 10964.77,6547.5 h60
  text "4.2" at 11614.6,6547.5 h60
  text "7" at 8765.34,6427.5 h60
  text "Mid Layer 2" at 9175.26,6427.5 h60
  text "Copper" at 10105,6427.5 h60
  text "2.80mil" at 10964.77,6427.5 h60
  text "8" at 8765.34,6307.5 h60
  text "Dielectric 3" at 9175.26,6307.5 h60
  text "FR-4 High TG" at 10105,6307.5 h60
  text "9.30mil" at 10964.77,6307.5 h60
  text "4.2" at 11614.6,6307.5 h60
  text "9" at 8765.34,6187.5 h60
  text "Bottom Layer" at 9175.26,6187.5 h60
  text "Copper" at 10105,6187.5 h60
  text "2.80mil" at 10964.77,6187.5 h60
  text "10" at 8765.34,6067.5 h60
  text "Bottom Solder" at 9175.26,6067.5 h60
  text "Solder Resist" at 10105,6067.5 h60
  text "0.40mil" at 10964.77,6067.5 h60
  text "3.5" at 11614.6,6067.5 h60
  text "11" at 8765.34,5947.5 h60
  text "Bottom Overlay" at 9175.26,5947.5 h60
  text ".Layer_Name" at 577,-1308.49 h60
M13 Component Bodies Top:
  text ".Layer_Name" at 577,-1308.49 h60
M14 Component Bodies Bottom:
  text ".Layer_Name" at 577,-1308.49 h60
M15 Courtyards Top:
  text ".Layer_Name" at 577,-1308.49 h60
M16 Courtyards Bottom:
  text ".Layer_Name" at 577,-1308.49 h60
Drill Drawing:
  lines w10: 5336.09,2521.06 5391.34,2521.06 5391.34,2576.31 5336.09,2576.31 5336.09,2521.06 ; 5336.09,2645.38 5391.34,2645.38 5391.34,2700.63 5336.09,2700.63 5336.09,2645.38 ; 5336.09,2783.51 5349.9,2783.51 5363.72,2769.7 5377.53,2783.51 5391.34,2783.51 5377.53,2797.32 5391.34,2811.14 5377.53,2811.14 5363.72,2824.95 5349.9,2811.14 5336.09,2811.14 5349.9,2797.32 5336.09,2783.51 ; 5336.09,2907.83 5349.9,2907.83 5349.9,2894.02 5377.53,2894.02 5377.53,2907.83 5391.34,2907.83 5391.34,2935.46 5377.53,2935.46 5377.53,2949.27 5349.9,2949.27 5349.9,2935.46 5336.09,2935.46 5336.09,2907.83 ; 5336.09,3018.34 5336.09,3032.15 5349.9,3045.96 5336.09,3059.78 5336.09,3073.59 5349.9,3073.59 5363.72,3059.78 5377.53,3073.59 5391.34,3073.59 5391.34,3059.78 5377.53,3045.96 5391.34,3032.15 5391.34,3018.34 5377.53,3018.34 5363.72,3032.15 5349.9,3018.34 5336.09,3018.34 ; 5336.09,3142.66 5363.72,3156.47 5391.34,3142.66 5377.53,3170.28 5391.34,3197.91 5363.72,3184.1 5336.09,3197.91 5349.9,3170.28 5336.09,3142.66 ; 5347.14,2656.43 5380.29,2656.43 5380.29,2689.58 5347.14,2689.58 5347.14,2656.43
  lines w12: 5286,2483.76 8517.49,2483.76 ; 5286,3229.68 8517.49,3229.68 ; 5623.86,2359.44 5623.86,3354 ; 5955.86,2359.44 5955.86,3354 ; 6592.43,2359.44 6592.43,3354 ; 6851.57,2359.44 6851.57,3354 ; 7226.72,2359.44 7226.72,3354 ; 7951.05,2359.44 7951.05,3354 ; 5286,2359.44 8517.49,2359.44 8517.49,3354 5286,3354 5286,2359.44
  text "Symbol" at 5360.59,3266.98 h72
  text "Quantity" at 5661.16,3266.98 h72
  text "Finished Hole Size" at 5993.16,3266.98 h72
  text "Plated" at 6629.72,3266.98 h72
  text "Hole Type" at 6888.86,3266.98 h72
  text "Drill Layer Pair" at 7264.02,3266.98 h72
  text "Hole Tolerance" at 7988.35,3266.98 h72
  text "8" at 5661.16,3142.66 h60
  text "8.00mil (0.203mm)" at 5993.16,3142.66 h60
  text "PTH" at 6629.72,3142.66 h60
  text "Round" at 6888.86,3142.66 h60
  text "Top Layer - Bottom Layer" at 7264.02,3142.66 h60
  text "10" at 5661.16,3018.34 h60
  text "10.00mil (0.254mm)" at 5993.16,3018.34 h60
  text "PTH" at 6629.72,3018.34 h60
  text "Round" at 6888.86,3018.34 h60
  text "Top Layer - Bottom Layer" at 7264.02,3018.34 h60
  text "197" at 5661.16,2894.02 h60
  text "12.00mil (0.305mm)" at 5993.16,2894.02 h60
  text "PTH" at 6629.72,2894.02 h60
  text "Round" at 6888.86,2894.02 h60
  text "Top Layer - Bottom Layer" at 7264.02,2894.02 h60
  text "15" at 5661.16,2769.7 h60
  text "40.00mil (1.016mm)" at 5993.16,2769.7 h60
  text "PTH" at 6629.72,2769.7 h60
  text "Round" at 6888.86,2769.7 h60
  text "Top Layer - Bottom Layer" at 7264.02,2769.7 h60
  text "8" at 5661.16,2645.38 h60
  text "49.21mil (1.250mm)" at 5993.16,2645.38 h60
  text "PTH" at 6629.72,2645.38 h60
  text "Round" at 6888.86,2645.38 h60
  text "Top Layer - Bottom Layer" at 7264.02,2645.38 h60
  text "14" at 5661.16,2521.06 h60
  text "63.00mil (1.600mm)" at 5993.16,2521.06 h60
  text "PTH" at 6629.72,2521.06 h60
  text "Round" at 6888.86,2521.06 h60
  text "Top Layer - Bottom Layer" at 7264.02,2521.06 h60
  text "252 Total" at 5661.16,2396.74 h60
  text ".Layer_Name" at 577,-1308.49 h60
M17 Embedded Cavity:
  text ".Layer_Name" at 577,-1308.49 h60
M18 Embedded Assembly:
  text ".Layer_Name" at 577,-1308.49 h60
M19 Embedded Keepout:
  text ".Layer_Name" at 577,-1308.49 h60

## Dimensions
0,-850 to 1000,-850 on M2 Board Dimensions
0,-25 to 3000,0 on M2 Board Dimensions
-25,0 to 0,3000 on M2 Board Dimensions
